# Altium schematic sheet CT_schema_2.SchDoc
size 383 x 329 mm
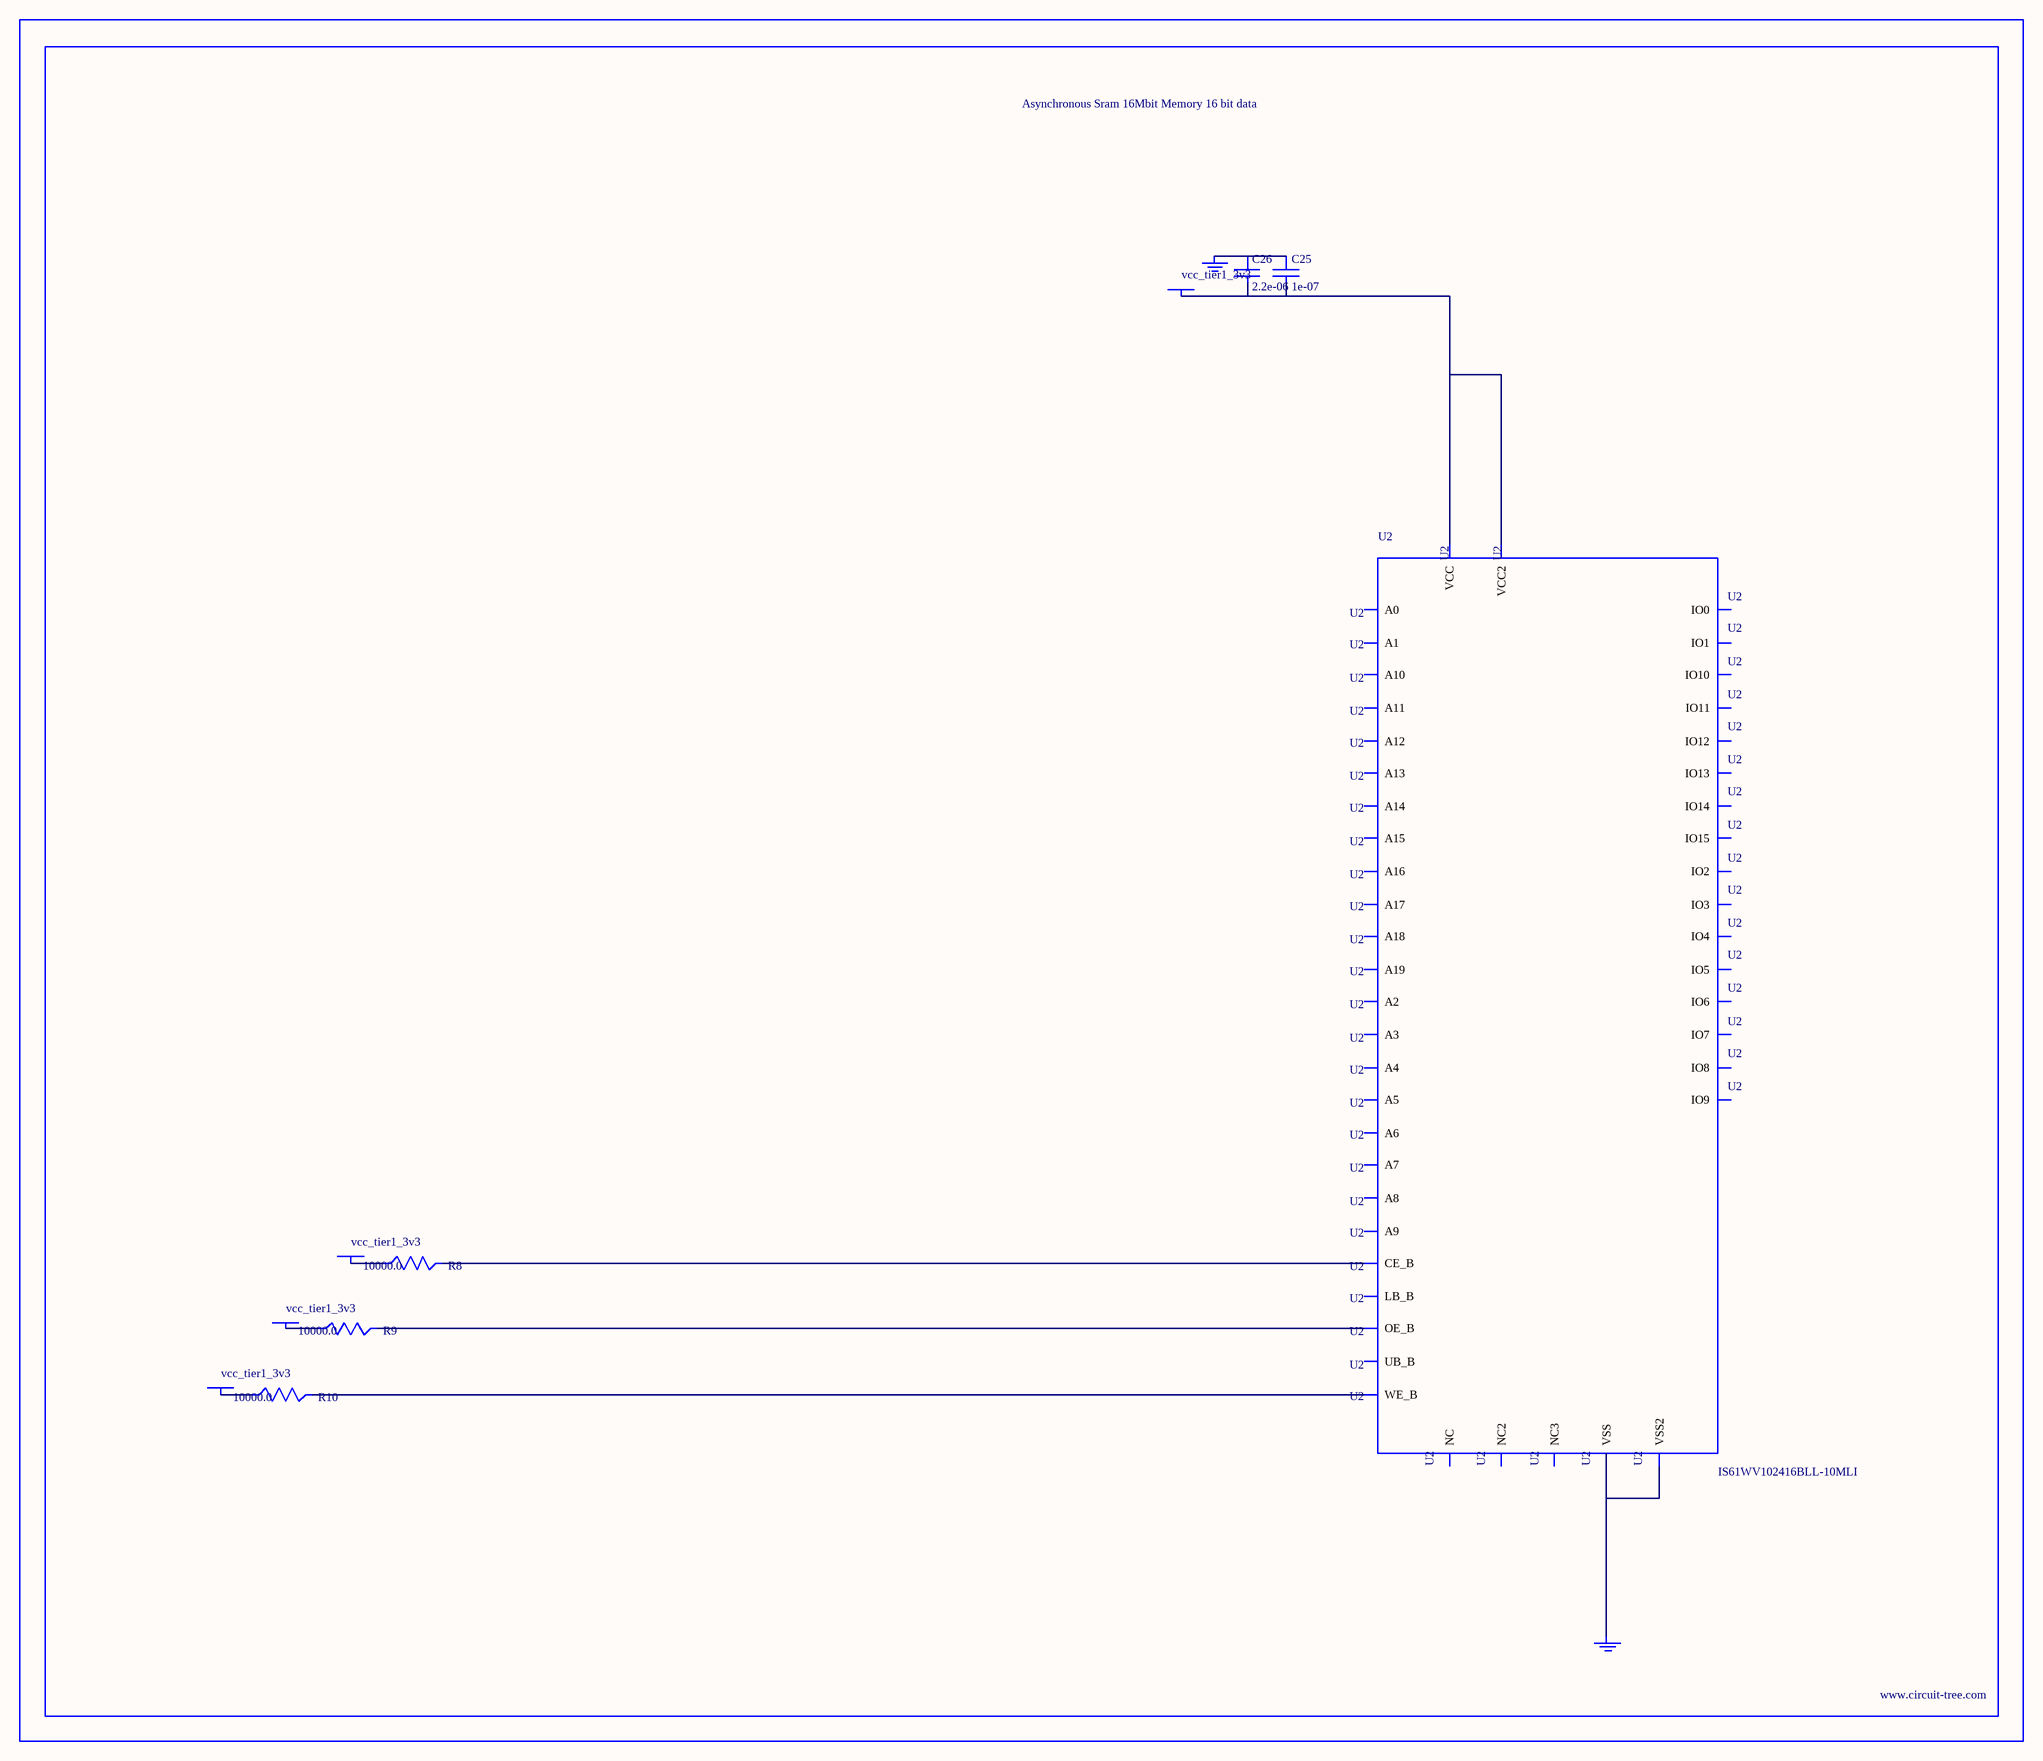
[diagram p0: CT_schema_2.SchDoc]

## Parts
BORDER1  (no value)
C25  1e-07  [C0402]
C26  2.2e-06  [C0603]
GND_INSTANCE_1_0  (no value)
GND_INSTANCE_1_1  (no value)
POWER_INSTANCE_1_0  vcc_tier1_3v3
POWER_INSTANCE_1_1  vcc_tier1_3v3
POWER_INSTANCE_1_2  vcc_tier1_3v3
POWER_INSTANCE_1_3  vcc_tier1_3v3
R8  10000.0  [R0603]
R9  10000.0  [R0603]
R10  10000.0  [R0603]
U2  IS61WV102416BLL-10MLI  [IS61WV102416BLL-10MLI]

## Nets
NetC25_1: C25.1 C26.1 GND_INSTANCE_1_0.0(GND)
NetC25_2: C25.2 C26.2 POWER_INSTANCE_1_0.0(PWR) U2.D6(VCC) U2.E1(VCC2)
NetGND_INSTANCE_1_1_0: GND_INSTANCE_1_1.0(GND) U2.D1(VSS) U2.E6(VSS2)
NetPOWER_INSTANCE_1_1_0: POWER_INSTANCE_1_1.0(PWR) R8.1
NetPOWER_INSTANCE_1_2_0: POWER_INSTANCE_1_2.0(PWR) R9.1
NetPOWER_INSTANCE_1_3_0: POWER_INSTANCE_1_3.0(PWR) R10.1
NetR8_2: R8.2 U2.B5(CE_B)
NetR9_2: R9.2 U2.A2(OE_B)
NetR10_2: R10.2 U2.G5(WE_B)

Not connected (* = marked no-connect by the designer): U2 A1(LB_B) A3(A0) A4(A1) A5(A2) A6(NC) B1(IO8) B2(UB_B) B3(A3) B4(A4) B6(IO0) C1(IO9) C2(IO10) C3(A5) C4(A6) C5(IO1) C6(IO2) D2(IO11) D3(A17) D4(A7) D5(IO3) E2(IO12) E3(NC2) E4(A16) E5(IO4) F1(IO14) F2(IO13) F3(A14) F4(A15) F5(IO5) F6(IO6) G1(IO15) G2(A19) G3(A12) G4(A13) G6(IO7) H1(A18) H2(A8) H3(A9) H4(A10) H5(A11) H6(NC3)

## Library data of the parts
BORDER1 = BORDER_PAGE1
C25 = C0402C104K3RACTU
C26 = C0603C225K8RACTU
GND_INSTANCE_1_0 GND_INSTANCE_1_1 = GND
POWER_INSTANCE_1_0-POWER_INSTANCE_1_3 = PWR
R8-R10 = RC0603JR-0710KL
